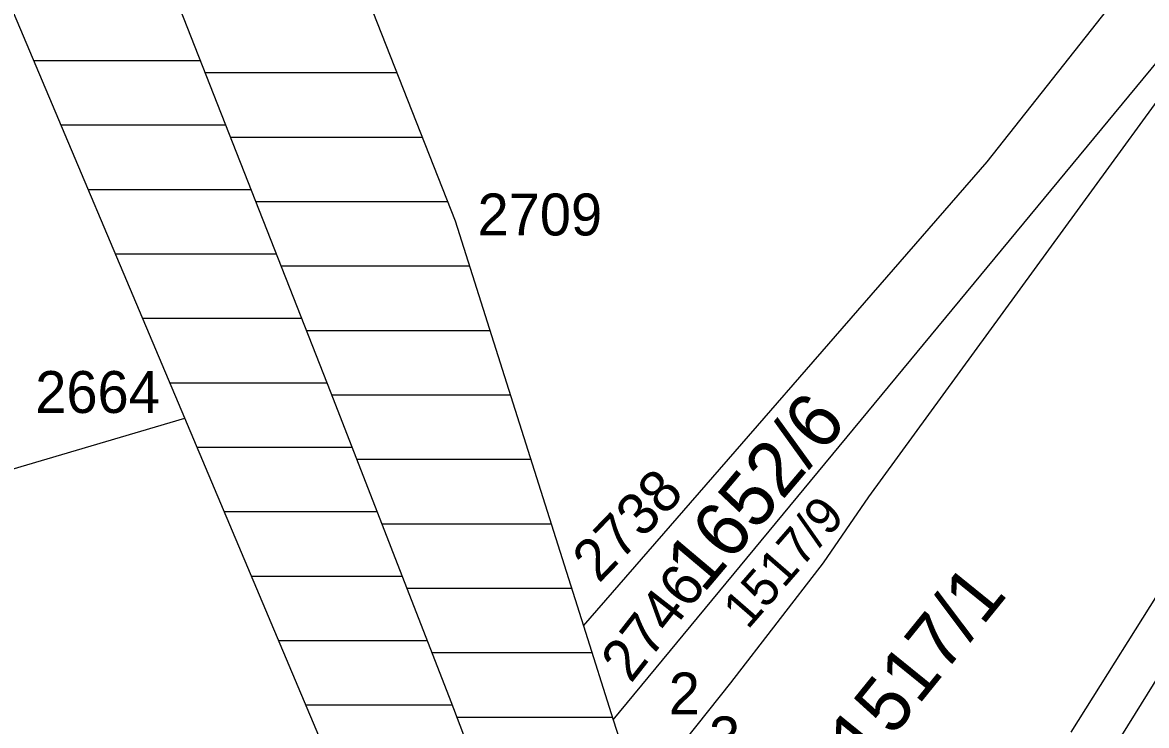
# Model space of a CAD drawing. Extents: x -553916 to -552953, y -1067469 to -1066637.
# Drawn here: x -553532.46 to -553497.58, y -1066968.69 to -1066946.87 of the extents above; entities that cross this region are included whole.
import ezdxf

# ---------------------------------------------------------------- set-up
doc = ezdxf.new("R2010")
doc.units = 0
for name, color, linetype in [('Hranice parcel', 7, 'Continuous'), ('Kolej', 7, 'Continuous'), ('Parcelní čísla', 7, 'Continuous'), ('Vrstva 1', 7, 'Continuous'), ('Vrstva 60', 7, 'Continuous')]:
    doc.layers.add(name, color=color, linetype=linetype)

msp = doc.modelspace()

# ---------------------------------------------------------------- linework, layer by layer
at = {"layer": 'Hranice parcel'}
for p, q in [((-553514.13, -1066968.51), (-553489.9, -1066939.2)), ((-553486.47, -1066947.45), (-553499.93, -1066968.9)), ((-553545.85, -1066964.59), (-553527.43, -1066959.15))]:
    msp.add_line(p, q, dxfattribs=at)
for points in [[(-553515.05, -1066965.6), (-553502.53, -1066951.2), (-553486.22, -1066930.56), (-553479.63, -1066908.8), (-553477.16, -1066903.7)], [(-553489.9, -1066939.2), (-553506.21, -1066961.59), (-553507.62, -1066963.64), (-553510.49, -1066967.37), (-553513.35, -1066970.96)], [(-553481.25, -1066991.64), (-553501.02, -1066983.66), (-553503.13, -1066976.7), (-553485.37, -1066948.09)]]:
    msp.add_lwpolyline(points, dxfattribs=at)
at = {"layer": 'Kolej'}
msp.add_lwpolyline([(-553503.324, -1067065.808), (-553502.678, -1067054.027), (-553502.762, -1067041.504), (-553503.626, -1067029.057), (-553504.756, -1067019.974), (-553506.183, -1067011.388), (-553508.328, -1067001.388), (-553510.948, -1066991.622), (-553512.921, -1066985.291), (-553515.647, -1066977.347), (-553517.422, -1066972.53), (-553519.157, -1066967.95), (-553522.886, -1066958.375), (-553529.101, -1066942.549), (-553538.686, -1066918.107), (-553542.908, -1066907.329), (-553546.692, -1066897.676), (-553555.025, -1066876.441), (-553564.644, -1066851.894), (-553574.241, -1066827.427), (-553583.19, -1066804.618)], dxfattribs=at)
at = {"layer": 'Vrstva 1'}
for p, q in [((-553527.43, -1066959.15), (-553535.26, -1066940.6)), ((-553532.114, -1066948.052), (-553526.94, -1066948.052)), ((-553526.792, -1066948.429), (-553520.852, -1066948.429)), ((-553531.27, -1066950.052), (-553526.155, -1066950.052)), ((-553526.006, -1066950.429), (-553520.065, -1066950.429)), ((-553530.426, -1066952.052), (-553525.369, -1066952.052)), ((-553525.221, -1066952.429), (-553519.277, -1066952.429)), ((-553529.582, -1066954.052), (-553524.584, -1066954.052)), ((-553524.436, -1066954.429), (-553518.596, -1066954.429)), ((-553528.738, -1066956.052), (-553523.798, -1066956.052)), ((-553523.65, -1066956.429), (-553517.961, -1066956.429)), ((-553527.893, -1066958.052), (-553523.013, -1066958.052)), ((-553522.865, -1066958.429), (-553517.326, -1066958.429)), ((-553527.049, -1066960.052), (-553522.233, -1066960.052)), ((-553522.086, -1066960.429), (-553516.691, -1066960.429)), ((-553526.204, -1066962.052), (-553521.454, -1066962.052)), ((-553521.307, -1066962.429), (-553516.057, -1066962.429)), ((-553525.359, -1066964.052), (-553520.675, -1066964.052)), ((-553520.528, -1066964.429), (-553515.422, -1066964.429)), ((-553515.05, -1066965.6), (-553514.13, -1066968.51)), ((-553524.514, -1066966.052), (-553519.896, -1066966.052)), ((-553519.749, -1066966.429), (-553514.788, -1066966.429)), ((-553523.67, -1066968.052), (-553519.118, -1066968.052)), ((-553518.976, -1066968.429), (-553514.156, -1066968.429)), ((-553514.13, -1066968.51), (-553513.35, -1066970.96))]:
    msp.add_line(p, q, dxfattribs=at)
for points in [[(-553537.18, -1066906.98), (-553519.04, -1066953.03), (-553515.05, -1066965.6)], [(-553521.68, -1066973.05), (-553522.23, -1066971.46), (-553527.43, -1066959.15)]]:
    msp.add_lwpolyline(points, dxfattribs=at)
at = {"layer": 'Vrstva 60'}
for p, q in [((-553519.04, -1066953.03), (-553519.04, -1066953.03)), ((-553527.43, -1066959.15), (-553527.43, -1066959.15)), ((-553515.05, -1066965.6), (-553515.05, -1066965.6)), ((-553514.13, -1066968.51), (-553514.13, -1066968.51)), ((-553511.542, -1066968.69), (-553511.542, -1066968.69))]:
    msp.add_line(p, q, dxfattribs=at)

# ---------------------------------------------------------------- texts
at = {"layer": 'Parcelní čísla'}
for s, height, rotation, p in [('1652/6', 1.7, 49.8322, (-553511.335, -1066964.618)), ('1517/9', 1.14, 49, (-553509.959, -1066965.739)), ('1517/1', 1.7, 51, (-553506.254, -1066970.044))]:
    msp.add_text(s, height=height, rotation=rotation, dxfattribs=at).set_placement(p)
at = {"layer": 'Vrstva 60'}
for s, p in [('2709', (-553518.342, -1066953.481)), ('2664', (-553532.068, -1066958.99)), ('2', (-553512.408, -1066968.347)), ('3', (-553511.159, -1066969.71))]:
    msp.add_text(s, height=1.3, dxfattribs=at).set_placement(p)
for s, rotation, p in [('2738', 45.924, (-553514.577, -1066964.298)), ('2746', 52.013, (-553513.583, -1066967.408))]:
    msp.add_text(s, height=1.3, rotation=rotation, dxfattribs=at).set_placement(p)

doc.saveas('drawing.dxf')
